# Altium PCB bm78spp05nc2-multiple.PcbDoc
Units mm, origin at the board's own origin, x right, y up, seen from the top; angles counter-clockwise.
Board outline 83.62 x 87.38 mm, 2 copper layers (Top Layer, Bottom Layer); 102 components, 12 nets, 410 pads, 156 vias.
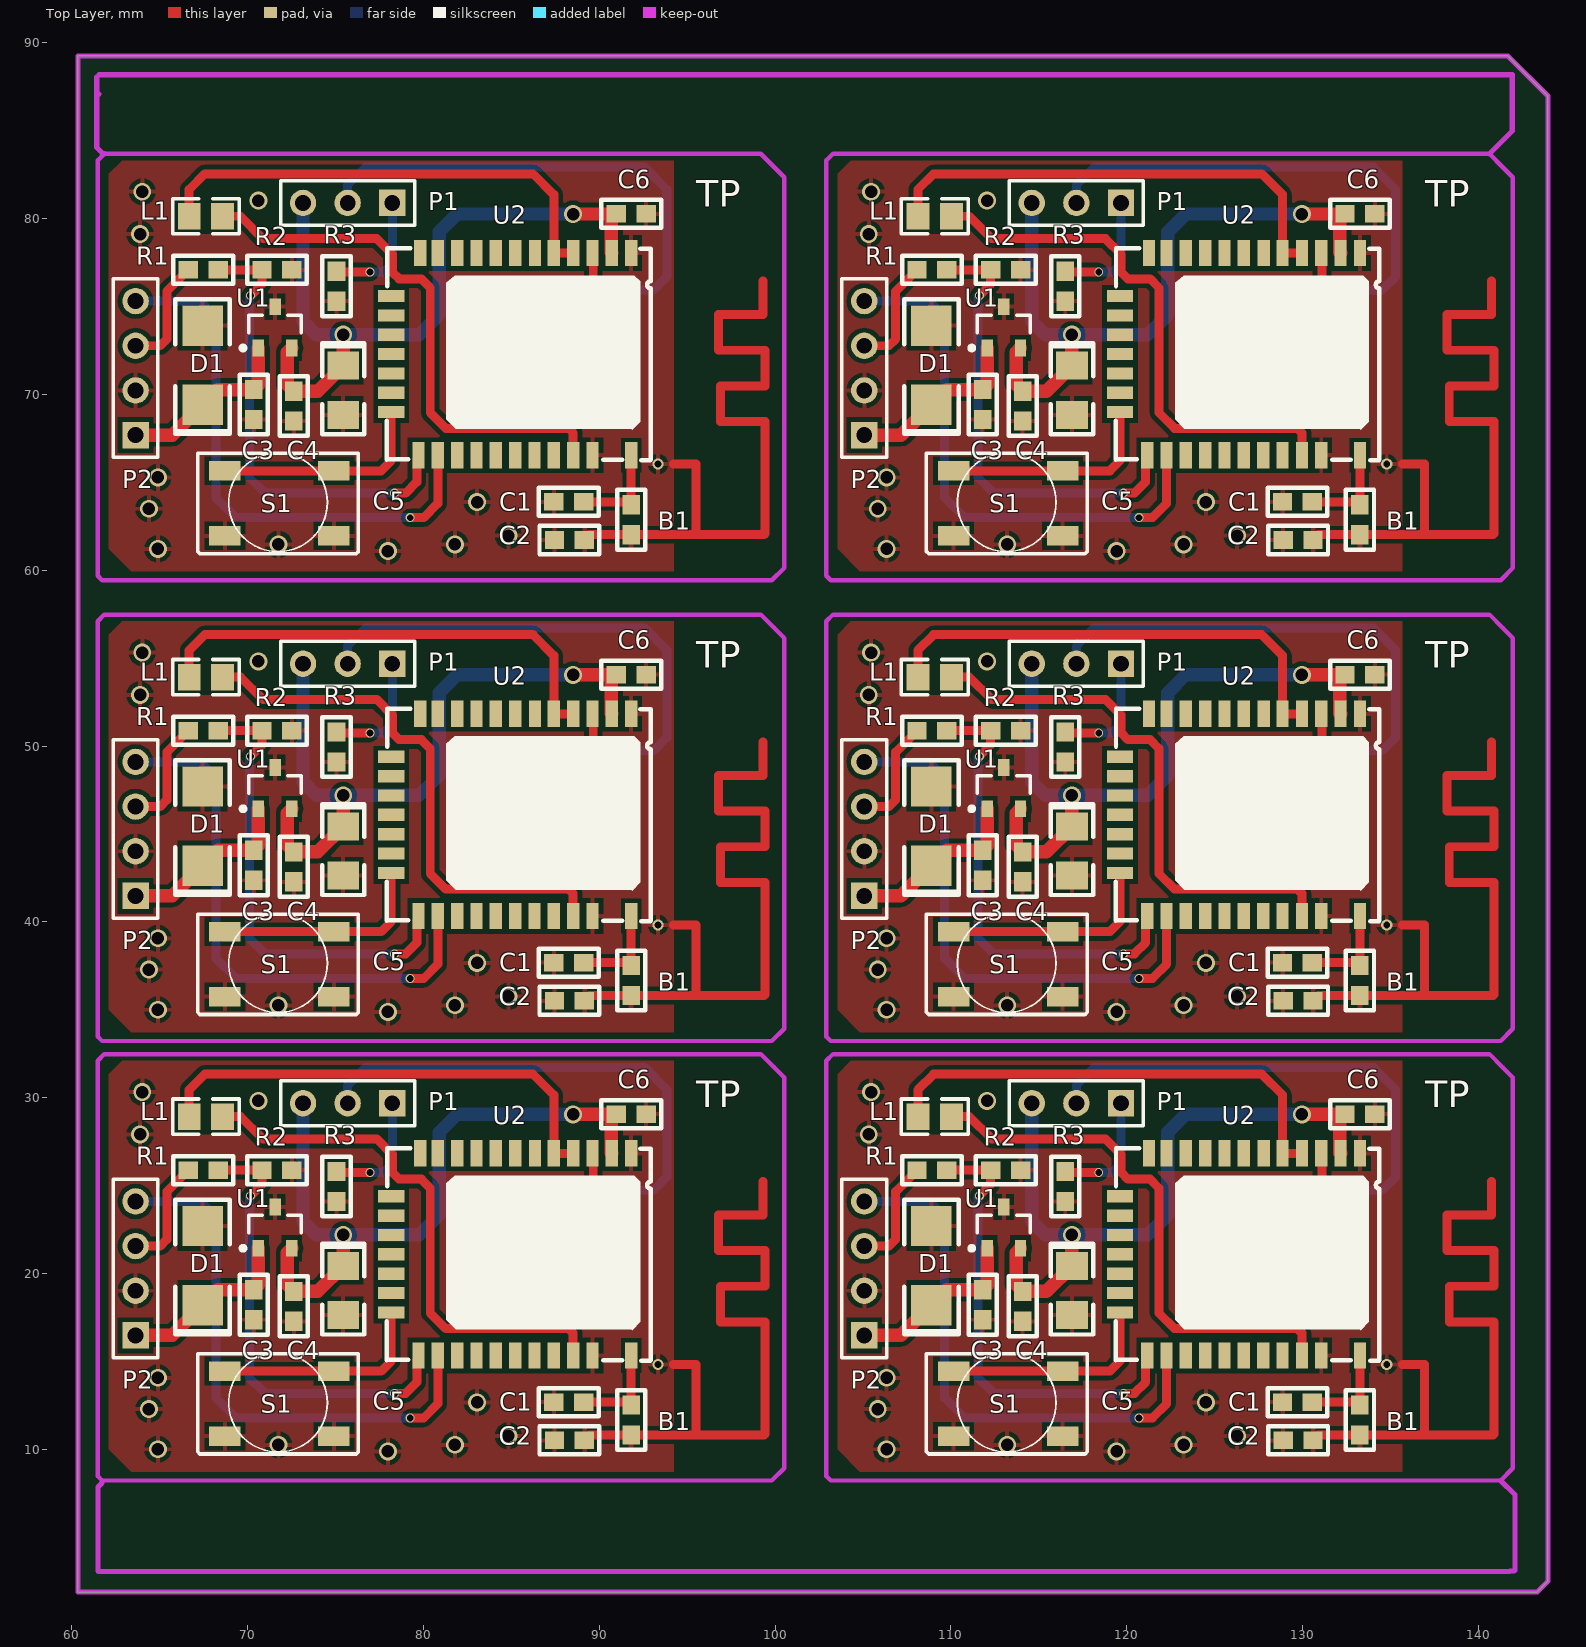
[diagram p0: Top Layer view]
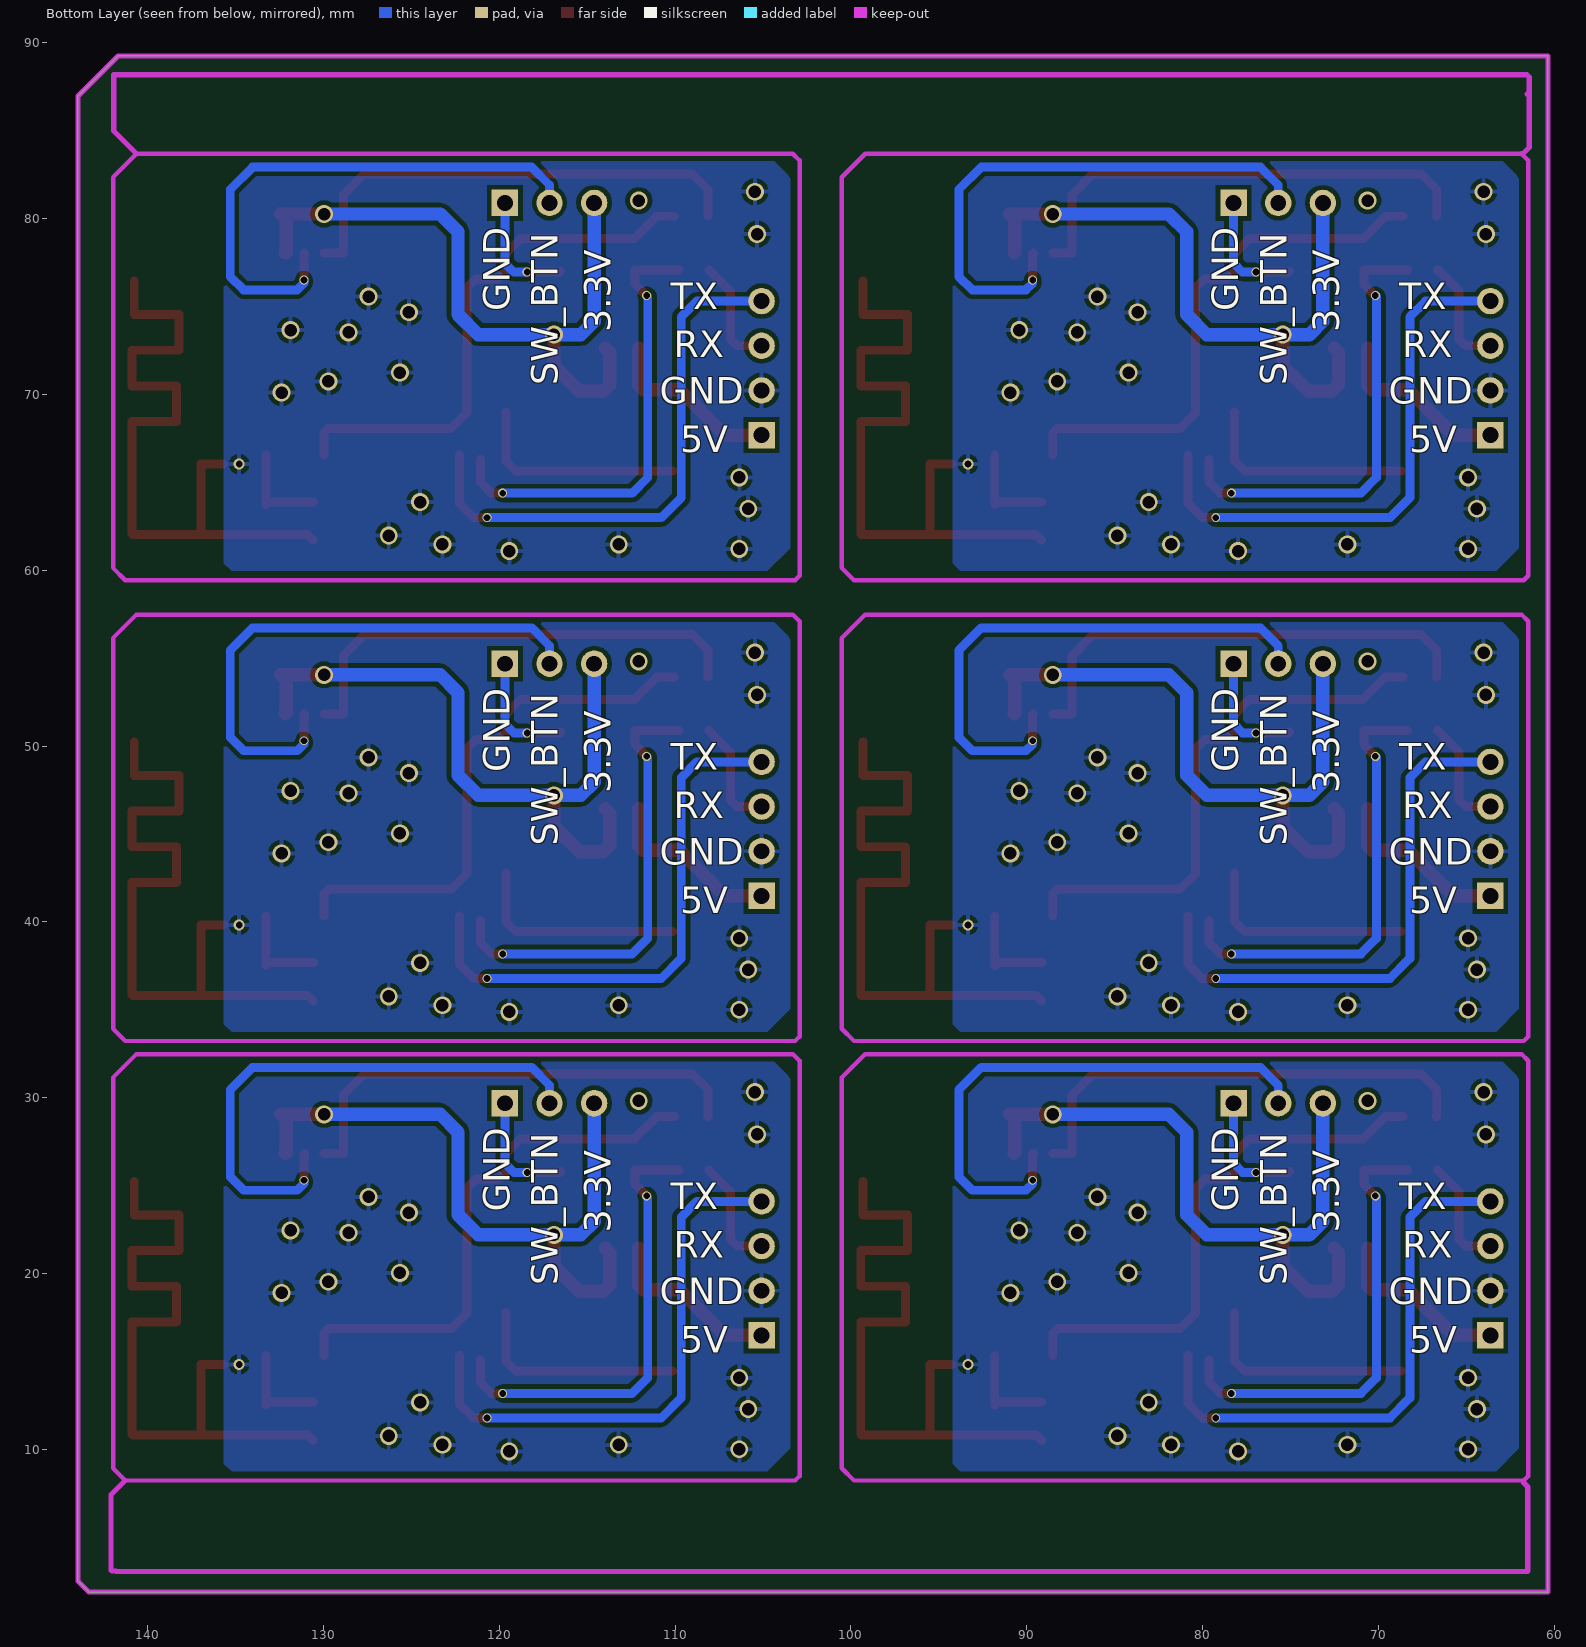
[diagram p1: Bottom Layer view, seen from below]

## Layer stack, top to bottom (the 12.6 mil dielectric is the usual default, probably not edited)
Top Solder: solder mask 0.0102, Solder Resist, Dk 3.5
Top Layer: signal copper 0.0356
Dielectric 1: dielectric 0.32, FR-4, Dk 4.8
Bottom Layer: signal copper 0.0356
Bottom Solder: solder mask 0.0102, Solder Resist, Dk 3.5

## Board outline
60.35,1.88 143.358,1.88 143.967,2.489 143.967,86.97 141.681,89.256 60.35,89.256

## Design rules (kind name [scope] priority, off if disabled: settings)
Clearance [All] p1: gap=0.254
PolygonConnect [All] p1: connectstyle=Relief reliefconductorwidth=0.254 reliefentries=4 polygonreliefangle="90 Angle" airgapwidth=0.254
RoutingVias [All] p1: holewidth=0.381 width=0.508 viastyle="Through Hole" minholewidth=0.381 minwidth=0.508 maxholewidth=0.711 maxwidth=1.016
SolderMaskExpansion [All] p1: expansion=0.102
Width [All] p1: maxlimit=1.016 minlimit=0.254 preferedwidth=0.508
30 further rules are at their usual default settings.

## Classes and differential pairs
component class BM78SPP05NC2: B1 C1 C2 C3 C4 C5 C6 D1 L1 P1 P2 R1 R2 R3 S1 U1 U2

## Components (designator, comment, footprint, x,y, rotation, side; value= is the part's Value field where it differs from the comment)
B1 "1nh" 0603 91.809,62.877 r270 top
B1 "1nh" 0603 133.262,62.877 r270 top
B1 "1nh" 0603 133.262,36.664 r270 top
B1 "1nh" 0603 91.809,36.664 r270 top
B1 "1nh" 0603 133.262,11.664 r270 top
B1 "1nh" 0603 91.809,11.664 r270 top
C1 "15pf" 0603 88.265,63.881 r0 top
C1 "15pf" 0603 129.718,63.881 r0 top
C1 "15pf" 0603 129.718,37.668 r0 top
C1 "15pf" 0603 88.265,37.668 r0 top
C1 "15pf" 0603 129.718,12.668 r0 top
C1 "15pf" 0603 88.265,12.668 r0 top
C2 "15pF" 0603 88.304,61.712 r0 top
C2 "15pF" 0603 129.757,61.712 r0 top
C2 "15pF" 0603 129.757,35.499 r0 top
C2 "15pF" 0603 88.304,35.499 r0 top
C2 "15pF" 0603 129.757,10.499 r0 top
C2 "15pF" 0603 88.304,10.499 r0 top
C3 "1uF" 0603 70.368,69.43 r90 top
C3 "1uF" 0603 111.821,69.43 r90 top
C3 "1uF" 0603 111.821,43.217 r90 top
C3 "1uF" 0603 70.368,43.217 r90 top
C3 "1uF" 0603 111.821,18.217 r90 top
C3 "1uF" 0603 70.368,18.217 r90 top
C4 "1uF" 0603 72.644,69.342 r90 top
C4 "1uF" 0603 114.097,69.342 r90 top
C4 "1uF" 0603 114.097,43.129 r90 top
C4 "1uF" 0603 72.644,43.129 r90 top
C4 "1uF" 0603 114.097,18.129 r90 top
C4 "1uF" 0603 72.644,18.129 r90 top
C5 "10uF/16V" 1206 75.438,70.231 r270 top
C5 "10uF/16V" 1206 116.891,70.231 r270 top
C5 "10uF/16V" 1206 116.891,44.018 r270 top
C5 "10uF/16V" 1206 75.438,44.018 r270 top
C5 "10uF/16V" 1206 116.891,19.018 r270 top
C5 "10uF/16V" 1206 75.438,19.018 r270 top
C6 "0.1uF" 0603 91.821,80.264 r0 top
C6 "0.1uF" 0603 133.274,80.264 r0 top
C6 "0.1uF" 0603 133.274,54.051 r0 top
C6 "0.1uF" 0603 91.821,54.051 r0 top
C6 "0.1uF" 0603 133.274,29.051 r0 top
C6 "0.1uF" 0603 91.821,29.051 r0 top
D1 "Schottky" DO214-AC 67.437,71.664 r270 top
D1 "Schottky" DO214-AC 108.89,71.664 r270 top
D1 "Schottky" DO214-AC 108.89,45.451 r270 top
D1 "Schottky" DO214-AC 67.437,45.451 r270 top
D1 "Schottky" DO214-AC 108.89,20.451 r270 top
D1 "Schottky" DO214-AC 67.437,20.451 r270 top
L1 "LED" 0805 67.63,80.137 r0 top
L1 "LED" 0805 109.083,80.137 r0 top
L1 "LED" 0805 109.083,53.924 r0 top
L1 "LED" 0805 67.63,53.924 r0 top
L1 "LED" 0805 109.083,28.924 r0 top
L1 "LED" 0805 67.63,28.924 r0 top
P1 "HC-SR501" Header3 75.692,78.629 r180 top
P1 "HC-SR501" Header3 117.145,78.629 r180 top
P1 "HC-SR501" Header3 117.145,52.416 r180 top
P1 "HC-SR501" Header3 75.692,52.416 r180 top
P1 "HC-SR501" Header3 117.145,27.416 r180 top
P1 "HC-SR501" Header3 75.692,27.416 r180 top
P2 "Header 4" HDR1X4 63.627,67.691 r90 top
P2 "Header 4" HDR1X4 105.08,67.691 r90 top
P2 "Header 4" HDR1X4 105.08,41.478 r90 top
P2 "Header 4" HDR1X4 63.627,41.478 r90 top
P2 "Header 4" HDR1X4 105.08,16.478 r90 top
P2 "Header 4" HDR1X4 63.627,16.478 r90 top
R1 "2.2K" 0603 67.476,77.079 r0 top
R1 "2.2K" 0603 108.929,77.079 r0 top
R1 "2.2K" 0603 108.929,50.866 r0 top
R1 "2.2K" 0603 67.476,50.866 r0 top
R1 "2.2K" 0603 108.929,25.866 r0 top
R1 "2.2K" 0603 67.476,25.866 r0 top
R2 "4.7K" 0603 71.667,77.099 r180 top
R2 "4.7K" 0603 113.12,77.099 r180 top
R2 "4.7K" 0603 113.12,50.886 r180 top
R2 "4.7K" 0603 71.667,50.886 r180 top
R2 "4.7K" 0603 113.12,25.886 r180 top
R2 "4.7K" 0603 71.667,25.886 r180 top
R3 "2.2K" 0603 75.067,76.161 r90 top
R3 "2.2K" 0603 116.52,76.161 r90 top
R3 "2.2K" 0603 116.52,49.948 r90 top
R3 "2.2K" 0603 75.067,49.948 r90 top
R3 "2.2K" 0603 116.52,24.948 r90 top
R3 "2.2K" 0603 75.067,24.948 r90 top
S1 "Button" BUtton-T4 74.907,61.959 r180 top
S1 "Button" BUtton-T4 116.36,61.959 r180 top
S1 "Button" BUtton-T4 116.36,35.746 r180 top
S1 "Button" BUtton-T4 74.907,35.746 r180 top
S1 "Button" BUtton-T4 116.36,10.746 r180 top
S1 "Button" BUtton-T4 74.907,10.746 r180 top
U1 "AP7313" AP7313-33SAG-7 71.562,73.819 r90 top
U1 "AP7313" AP7313-33SAG-7 113.015,73.819 r90 top
U1 "AP7313" AP7313-33SAG-7 113.015,47.606 r90 top
U1 "AP7313" AP7313-33SAG-7 71.562,47.606 r90 top
U1 "AP7313" AP7313-33SAG-7 113.015,22.606 r90 top
U1 "AP7313" AP7313-33SAG-7 71.562,22.606 r90 top
U2 "BM78SPP05NC2" BM78SPP05NC2 77.919,78.298 r270 top
U2 "BM78SPP05NC2" BM78SPP05NC2 119.372,78.298 r270 top
U2 "BM78SPP05NC2" BM78SPP05NC2 119.372,52.085 r270 top
U2 "BM78SPP05NC2" BM78SPP05NC2 77.919,52.085 r270 top
U2 "BM78SPP05NC2" BM78SPP05NC2 119.372,27.085 r270 top
U2 "BM78SPP05NC2" BM78SPP05NC2 77.919,27.085 r270 top

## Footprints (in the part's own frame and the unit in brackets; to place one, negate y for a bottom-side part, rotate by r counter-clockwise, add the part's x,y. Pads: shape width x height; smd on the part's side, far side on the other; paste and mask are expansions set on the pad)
0603 [mm]
  rect 1.1x1 smd: 1(-0.85,0.01) 2(0.85,0.01)
  silkscreen extent -1.7,-0.79 1.7,0.81
0805 [mm]
  rect 1.3x1.5 smd: 1(-0.95,0) 2(0.95,0)
  silkscreen extent -1.9,-1 1.9,1
1206 [mm]
  rect 1.6x1.8 smd: 1(-1.41,0) 2(1.39,0)
  silkscreen extent -2.68,-1.2 2.49,1.2
AP7313-33SAG-7 [mm] "SOT23, 3-Leads, Body 2.90x2.40mm, Pitch 0.95mm, IPC Medium Density"
  rect 0.95x0.65 smd: 1(-1.175,0.95) 2(-1.175,-0.95) 3(1.175,0)
  silkscreen extent -1.3,-1.5 0.7,1.95
BM78SPP05NC2 [mm]
  rect 1.5x0.7 smd: 1(0.25,13.9) 2(0.25,12.8) 3(0.25,11.7) 4(0.25,10.6) 5(0.25,9.5) 6(0.25,8.43) 7(0.25,7.3) 8(0.25,6.2) 9(0.25,5.1) 10(0.25,4) 11(0.25,2.9) 12(0.25,1.9) 20(11.75,1.8) 21(11.75,2.9) 22(11.75,4) 23(11.75,5.1) 24(11.75,6.2) 25(11.75,7.3) 26(11.75,8.4) 27(11.75,9.5) 28(11.75,10.6) 29(11.75,11.7) 30(11.75,13.9)
  rect 0.7x1.5 smd: 13(2.7,0.25) 14(3.8,0.25) 15(4.9,0.25) 16(6,0.25) 17(7.1,0.25) 18(8.2,0.25) 19(9.3,0.25)
  silkscreen extent -0.03,0 12.04,15.01
BUtton-T4 [mm] "4*4*1.5"
  rect 1.8x1.1 smd: 1(0,0) 1(6.2,0) 2(0,-3.7) 2(6.2,-3.7)
  silkscreen extent -1.4,-4.71 7.75,1.02
DO214-AC [mm]
  rect 2.3x2.3 smd: 1(-2.25,0) 2(2.25,0)
  silkscreen extent -3.75,-1.55 3.9,1.55
HDR1X4 [mm] "Connector; Header; 4 Position"
  rect 1.5x1.5 hole 0.9: 1(0,0)
  round 1.5 hole 0.9: 2(2.54,0) 3(5.08,0) 4(7.62,0)
  silkscreen extent -1.27,-1.27 8.89,1.27
Header3 [mm]
  rect 1.5x1.5 hole 0.9: 1(-2.54,-2.27)
  round 1.5 hole 0.9: 2(0,-2.27) 3(2.54,-2.27)
  silkscreen extent -3.81,-3.54 3.81,-1

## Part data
B1 B1 B1 B1 B1 B1: library part Bead
C1 C1 C1 C1 C1 C1 C2 C2 C2 C2 C2 C2 C3 C3 C3 C3 C3 C3 C4 C4 C4 C4 C4 C4 C6 C6 C6 C6 C6 C6: library part Cap1, "ceramic"
C5 C5 C5 C5 C5 C5: library part Cap3, "aluminum"
D1 D1 D1 D1 D1 D1: library part B340A-13-F
P1 P1 P1 P1 P1 P1: library part "Header 3", "Header, 3-Pin"
P2 P2 P2 P2 P2 P2: "Header, 4-Pin"
R1 R1 R1 R1 R1 R1 R2 R2 R2 R2 R2 R2 R3 R3 R3 R3 R3 R3: library part Res
U1 U1 U1 U1 U1 U1: library part AP7313-33SAG-7

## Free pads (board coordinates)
  round 1.524 on Keep-Out: 3(63.602,86.03) 4(138.278,5.817)

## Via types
v1: diameter 1.016, hole 0.711, Top Layer to Bottom Layer, 120 vias
v2: diameter 0.508, hole 0.381, Top Layer to Bottom Layer, 30 vias
v3: diameter 0.635, hole 0.381, Top Layer to Bottom Layer, 6 vias

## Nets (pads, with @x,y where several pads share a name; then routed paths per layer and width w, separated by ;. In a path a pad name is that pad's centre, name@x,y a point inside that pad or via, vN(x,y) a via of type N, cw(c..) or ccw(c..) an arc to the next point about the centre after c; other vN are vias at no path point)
3.3V: C4.2@72.634,70.192 C5.1@75.438,71.641 C6.1@90.971,80.274 P1.3@73.152,80.899 U1.2@72.512,72.644 U2.2@90.719,78.048 | length 40.7
  Top Layer w0.762: U1.2@72.512,72.644 72.263,72.395 72.263,70.563 72.634,70.192 73.989,70.192 75.438,71.641 v1(75.438,73.406) ; v1(88.519,80.264) C6.1@90.961,80.264 ; U2.2@90.719,78.048 90.678,78.089 90.678,79.981 C6.1@90.961,80.264 ; C6.1@90.971,80.274 C6.1@90.961,80.264
  Bottom Layer w0.762: P1.3@73.152,80.899 73.152,74.168 73.914,73.406 v1(75.438,73.406) 79.756,73.406 80.899,74.549 80.899,79.248 81.915,80.264 v1(88.519,80.264)
5V: C3.2@70.358,70.28 D1.2@67.437,69.414 P2.1@63.627,67.691 U1.1@70.612,72.644 | length 10.3
  Top Layer w0.762: P2.1@63.627,67.691 65.714,67.691 67.437,69.414 68.303,70.28 70.358,70.28 70.612,70.534 U1.1@70.612,72.644
ANT: B1.2@91.819,62.027 C1.1@87.415,63.891 C2.1@87.454,61.722 C2.2@89.154,61.722 C3.1@70.358,68.58 C4.1@72.634,68.492 C5.2@75.438,68.841 C6.2@92.671,80.274 D1.1@67.437,73.914 P2.2@63.627,70.231 R2.1@72.517,77.089 R3.1@75.057,75.311 S1.1@68.707,61.959 S1.1@74.907,61.959 U1.3@71.562,74.994 U2.1@91.819,78.048 U2.29@89.619,66.548 | length 40.4
  Top Layer w0.508: C2.2@89.154,61.722 89.459,62.027 91.819,62.027 95.504,62.027 ; 94.234,66.04 95.504,66.04 95.504,62.027 ; 99.314,76.454 99.314,74.549 96.774,74.549 96.774,72.517 99.441,72.517 99.441,70.485 96.901,70.485 96.901,68.453 99.441,68.453 99.441,62.078 99.39,62.027 95.504,62.027
  other v1: 77.978,61.087 64.897,61.214 71.755,61.468 81.788,61.468 84.836,61.976 64.389,63.5 83.058,63.881 64.897,65.278 90.932,70.104 88.265,70.739 84.201,71.247 87.122,73.533 90.424,73.66 83.693,74.676 85.979,75.565 63.881,79.121 64.008,81.534
  other v3: 93.345,66.04
LDO33_O: L1.1@66.68,80.137 U2.4@88.519,78.048 U2.5@87.419,78.048 | length 27.5
  Top Layer w0.508: L1.1@66.68,80.137 66.675,80.137 66.675,81.661 67.564,82.55 86.233,82.55 87.419,81.364 87.419,78.048 U2.4@88.519,78.048
LED1: L1.2@68.58,80.137 U2.28@88.519,66.548 | length 31.1
  Top Layer w0.508: L1.2@68.58,80.137 69.596,80.137 70.866,78.867 77.343,78.867 78.232,77.978 78.232,76.962 78.613,76.581 79.883,76.581 80.391,76.073 80.391,68.961 81.28,68.072 88.265,68.072 88.519,67.818 U2.28@88.519,66.548
NetB1_1: B1.1@91.819,63.727 C1.2@89.115,63.891 U2.30@91.819,66.548 | length 5.6
  Top Layer w0.508: C1.2@89.115,63.891 91.655,63.891 91.819,63.727 U2.30@91.819,66.548
NetP1_1: P1.1@78.232,80.899 R3.2@75.057,77.011 | length 6.8
  Top Layer w0.508: R3.2@75.057,77.011 75.106,76.962 v2(76.962,76.962)
  Bottom Layer w0.508: v2(76.962,76.962) 77.724,76.962 78.232,77.47 P1.1@78.232,80.899
NetR1_2: R1.2@68.326,77.089 R2.2@70.817,77.089 U2.20@79.719,66.548 | length 26
  Top Layer w0.508: R1.2@68.326,77.089 70.817,77.089 70.817,76.278 v2(70.168,75.629) ; v2(78.359,64.389) 78.994,64.389 79.629,65.024 U2.20@79.629,66.294
  Bottom Layer w0.508: v2(70.168,75.629) 70.104,75.565 70.104,65.278 70.993,64.389 v2(78.359,64.389)
NetS1_2: S1.2@68.707,65.659 S1.2@74.907,65.659 U2.19@78.169,68.998 | length 12.5
  Top Layer w0.508: S1.2@68.707,65.659 74.907,65.659 77.597,65.659 78.169,66.231 U2.19@78.169,68.998
RX: P2.3@63.627,72.771 R1.1@66.626,77.089 | length 6.4
  Top Layer w0.508: P2.3@63.627,72.771 65.024,72.771 65.405,73.152 65.405,75.868 R1.1@66.626,77.089
SW_BTN: P1.2@75.692,80.899 U2.3@89.619,78.048 | length 31.5
  Top Layer w0.508: U2.3@89.619,78.048 89.662,78.005 v2(89.662,76.517)
  Bottom Layer w0.508: P1.2@75.692,80.899 75.692,81.915 76.708,82.931 92.583,82.931 93.853,81.661 93.853,76.708 93.091,75.946 90.043,75.946 89.662,76.327 v2(89.662,76.517)
TX: P2.4@63.627,75.311 U2.21@80.819,66.548 | length 31.4
  Top Layer w0.508: v2(79.248,62.992) 80.01,62.992 80.819,63.801 U2.21@80.819,66.548
  Bottom Layer w0.508: P2.4@63.627,75.311 67.31,75.311 68.199,74.422 68.199,64.135 69.342,62.992 v2(79.248,62.992)
pads on no net: B1.1@91.819,12.514 B1.1@91.819,37.514 B1.1@133.272,12.514 B1.1@133.272,37.514 B1.1@133.272,63.727 B1.2@91.819,10.814 B1.2@91.819,35.814 B1.2@133.272,10.814 B1.2@133.272,35.814 B1.2@133.272,62.027 C1.1@87.415,12.678 C1.1@87.415,37.678 C1.1@128.868,12.678 C1.1@128.868,37.678 C1.1@128.868,63.891 C1.2@89.115,12.678 C1.2@89.115,37.678 C1.2@130.568,12.678 C1.2@130.568,37.678 C1.2@130.568,63.891 C2.1@87.454,10.509 C2.1@87.454,35.509 C2.1@128.907,10.509 C2.1@128.907,35.509 C2.1@128.907,61.722 C2.2@89.154,10.509 C2.2@89.154,35.509 C2.2@130.607,10.509 C2.2@130.607,35.509 C2.2@130.607,61.722 C3.1@70.358,17.367 C3.1@70.358,42.367 C3.1@111.811,17.367 C3.1@111.811,42.367 C3.1@111.811,68.58 C3.2@70.358,19.067 C3.2@70.358,44.067 C3.2@111.811,19.067 C3.2@111.811,44.067 C3.2@111.811,70.28 C4.1@72.634,17.279 C4.1@72.634,42.279 C4.1@114.087,17.279 C4.1@114.087,42.279 C4.1@114.087,68.492 C4.2@72.634,18.979 C4.2@72.634,43.979 C4.2@114.087,18.979 C4.2@114.087,43.979 C4.2@114.087,70.192 C5.1@75.438,20.428 C5.1@75.438,45.428 C5.1@116.891,20.428 C5.1@116.891,45.428 C5.1@116.891,71.641 C5.2@75.438,17.628 C5.2@75.438,42.628 C5.2@116.891,17.628 C5.2@116.891,42.628 C5.2@116.891,68.841 C6.1@90.971,29.061 C6.1@90.971,54.061 C6.1@132.424,29.061 C6.1@132.424,54.061 C6.1@132.424,80.274 C6.2@92.671,29.061 C6.2@92.671,54.061 C6.2@134.124,29.061 C6.2@134.124,54.061 C6.2@134.124,80.274 D1.1@67.437,22.701 D1.1@67.437,47.701 D1.1@108.89,22.701 D1.1@108.89,47.701 D1.1@108.89,73.914 D1.2@67.437,18.201 D1.2@67.437,43.201 D1.2@108.89,18.201 D1.2@108.89,43.201 D1.2@108.89,69.414 L1.1@66.68,28.924 L1.1@66.68,53.924 L1.1@108.133,28.924 L1.1@108.133,53.924 L1.1@108.133,80.137 L1.2@68.58,28.924 L1.2@68.58,53.924 L1.2@110.033,28.924 L1.2@110.033,53.924 L1.2@110.033,80.137 P1.1@78.232,29.686 P1.1@78.232,54.686 P1.1@119.685,29.686 P1.1@119.685,54.686 P1.1@119.685,80.899 P1.2@75.692,29.686 P1.2@75.692,54.686 P1.2@117.145,29.686 P1.2@117.145,54.686 P1.2@117.145,80.899 P1.3@73.152,29.686 P1.3@73.152,54.686 P1.3@114.605,29.686 P1.3@114.605,54.686 P1.3@114.605,80.899 P2.1@63.627,16.478 P2.1@63.627,41.478 P2.1@105.08,16.478 P2.1@105.08,41.478 P2.1@105.08,67.691 P2.2@63.627,19.018 P2.2@63.627,44.018 P2.2@105.08,19.018 P2.2@105.08,44.018 P2.2@105.08,70.231 P2.3@63.627,21.558 P2.3@63.627,46.558 P2.3@105.08,21.558 P2.3@105.08,46.558 P2.3@105.08,72.771 P2.4@63.627,24.098 P2.4@63.627,49.098 P2.4@105.08,24.098 P2.4@105.08,49.098 P2.4@105.08,75.311 R1.1@66.626,25.876 R1.1@66.626,50.876 R1.1@108.079,25.876 R1.1@108.079,50.876 R1.1@108.079,77.089 R1.2@68.326,25.876 R1.2@68.326,50.876 R1.2@109.779,25.876 R1.2@109.779,50.876 R1.2@109.779,77.089 R2.1@72.517,25.876 R2.1@72.517,50.876 R2.1@113.97,25.876 R2.1@113.97,50.876 R2.1@113.97,77.089 R2.2@70.817,25.876 R2.2@70.817,50.876 R2.2@112.27,25.876 R2.2@112.27,50.876 R2.2@112.27,77.089 R3.1@75.057,24.098 R3.1@75.057,49.098 R3.1@116.51,24.098 R3.1@116.51,49.098 R3.1@116.51,75.311 R3.2@75.057,25.798 R3.2@75.057,50.798 R3.2@116.51,25.798 R3.2@116.51,50.798 R3.2@116.51,77.011 S1.1@68.707,10.746 S1.1@68.707,35.746 S1.1@74.907,10.746 S1.1@74.907,35.746 S1.1@110.16,10.746 S1.1@110.16,35.746 S1.1@110.16,61.959 S1.1@116.36,10.746 S1.1@116.36,35.746 S1.1@116.36,61.959 S1.2@68.707,14.446 S1.2@68.707,39.446 S1.2@74.907,14.446 S1.2@74.907,39.446 S1.2@110.16,14.446 S1.2@110.16,39.446 S1.2@110.16,65.659 S1.2@116.36,14.446 S1.2@116.36,39.446 S1.2@116.36,65.659 U1.1@70.612,21.431 U1.1@70.612,46.431 U1.1@112.065,21.431 U1.1@112.065,46.431 U1.1@112.065,72.644 U1.2@72.512,21.431 U1.2@72.512,46.431 U1.2@113.965,21.431 U1.2@113.965,46.431 U1.2@113.965,72.644 U1.3@71.562,23.781 U1.3@71.562,48.781 U1.3@113.015,23.781 U1.3@113.015,48.781 U1.3@113.015,74.994 U2.1@91.819,26.835 U2.1@91.819,51.835 U2.1@133.272,26.835 U2.1@133.272,51.835 U2.1@133.272,78.048 U2.2@90.719,26.835 U2.2@90.719,51.835 U2.2@132.172,26.835 U2.2@132.172,51.835 U2.2@132.172,78.048 U2.3@89.619,26.835 U2.3@89.619,51.835 U2.3@131.072,26.835 U2.3@131.072,51.835 U2.3@131.072,78.048 U2.4@88.519,26.835 U2.4@88.519,51.835 U2.4@129.972,26.835 U2.4@129.972,51.835 U2.4@129.972,78.048 U2.5@87.419,26.835 U2.5@87.419,51.835 U2.5@128.872,26.835 U2.5@128.872,51.835 U2.5@128.872,78.048 U2.6 U2.7 U2.8 U2.9 U2.10 U2.11 U2.12 U2.13 U2.14 U2.15 U2.16 U2.17 U2.18 U2.19@78.169,17.785 U2.19@78.169,42.785 U2.19@119.622,17.785 U2.19@119.622,42.785 U2.19@119.622,68.998 U2.20@79.719,15.335 U2.20@79.719,40.335 U2.20@121.172,15.335 U2.20@121.172,40.335 U2.20@121.172,66.548 U2.21@80.819,15.335 U2.21@80.819,40.335 U2.21@122.272,15.335 U2.21@122.272,40.335 U2.21@122.272,66.548 U2.22 U2.23 U2.24 U2.25 U2.26 U2.27 U2.28@88.519,15.335 U2.28@88.519,40.335 U2.28@129.972,15.335 U2.28@129.972,40.335 U2.28@129.972,66.548 U2.29@89.619,15.335 U2.29@89.619,40.335 U2.29@131.072,15.335 U2.29@131.072,40.335 U2.29@131.072,66.548 U2.30@91.819,15.335 U2.30@91.819,40.335 U2.30@133.272,15.335 U2.30@133.272,40.335 U2.30@133.272,66.548
copper on no net: | length 1350.7
  Top Layer w0.508: 63.627,21.558 65.024,21.558 65.405,21.939 65.405,24.655 66.626,25.876 ; 63.627,46.558 65.024,46.558 65.405,46.939 65.405,49.655 66.626,50.876 ; 66.68,28.924 66.675,28.924 66.675,30.448 67.564,31.337 86.233,31.337 87.419,30.151 87.419,26.835 88.519,26.835 ; 66.68,53.924 66.675,53.924 66.675,55.448 67.564,56.337 86.233,56.337 87.419,55.151 87.419,51.835 88.519,51.835 ; 68.326,25.876 70.817,25.876 70.817,25.065 v2(70.168,24.416) ; 68.326,50.876 70.817,50.876 70.817,50.065 v2(70.168,49.416) ; 68.58,28.924 69.596,28.924 70.866,27.654 77.343,27.654 78.232,26.765 78.232,25.749 78.613,25.368 79.883,25.368 80.391,24.86 80.391,17.748 81.28,16.859 88.265,16.859 88.519,16.605 88.519,15.335 ; 68.58,53.924 69.596,53.924 70.866,52.654 77.343,52.654 78.232,51.765 78.232,50.749 78.613,50.368 79.883,50.368 80.391,49.86 80.391,42.748 81.28,41.859 88.265,41.859 88.519,41.605 88.519,40.335 ; 68.707,14.446 74.907,14.446 77.597,14.446 78.169,15.018 78.169,17.785 ; 68.707,39.446 74.907,39.446 77.597,39.446 78.169,40.018 78.169,42.785 ; 75.057,25.798 75.106,25.749 v2(76.962,25.749) ; 75.057,50.798 75.106,50.749 v2(76.962,50.749) ; v2(78.359,13.176) 78.994,13.176 79.629,13.811 79.629,15.081 ; v2(78.359,38.176) 78.994,38.176 79.629,38.811 79.629,40.081 ; v2(79.248,11.779) 80.01,11.779 80.819,12.588 80.819,15.335 ; v2(79.248,36.779) 80.01,36.779 80.819,37.588 80.819,40.335 ; 89.115,12.678 91.655,12.678 91.819,12.514 91.819,15.335 ; 89.115,37.678 91.655,37.678 91.819,37.514 91.819,40.335 ; 89.154,10.509 89.459,10.814 91.819,10.814 95.504,10.814 ; 89.154,35.509 89.459,35.814 91.819,35.814 95.504,35.814 ; 89.619,26.835 89.662,26.792 v2(89.662,25.305) ; 89.619,51.835 89.662,51.792 v2(89.662,50.305) ; 94.234,14.827 95.504,14.827 95.504,10.814 ; 94.234,39.827 95.504,39.827 95.504,35.814 ; 99.314,25.241 99.314,23.336 96.774,23.336 96.774,21.304 99.441,21.304 99.441,19.272 96.901,19.272 96.901,17.24 99.441,17.24 99.441,10.865 99.39,10.814 95.504,10.814 ; 99.314,50.241 99.314,48.336 96.774,48.336 96.774,46.304 99.441,46.304 99.441,44.272 96.901,44.272 96.901,42.24 99.441,42.24 99.441,35.865 99.39,35.814 95.504,35.814 ; 105.08,21.558 106.477,21.558 106.858,21.939 106.858,24.655 108.079,25.876 ; 105.08,46.558 106.477,46.558 106.858,46.939 106.858,49.655 108.079,50.876 ; 105.08,72.771 106.477,72.771 106.858,73.152 106.858,75.868 108.079,77.089 ; 108.133,28.924 108.128,28.924 108.128,30.448 109.017,31.337 127.686,31.337 128.872,30.151 128.872,26.835 129.972,26.835 ; 108.133,53.924 108.128,53.924 108.128,55.448 109.017,56.337 127.686,56.337 128.872,55.151 128.872,51.835 129.972,51.835 ; 108.133,80.137 108.128,80.137 108.128,81.661 109.017,82.55 127.686,82.55 128.872,81.364 128.872,78.048 129.972,78.048 ; 109.779,25.876 112.27,25.876 112.27,25.065 v2(111.62,24.416) ; 109.779,50.876 112.27,50.876 112.27,50.065 v2(111.62,49.416) ; 109.779,77.089 112.27,77.089 112.27,76.278 v2(111.62,75.629) ; 110.033,28.924 111.049,28.924 112.319,27.654 118.796,27.654 119.685,26.765 119.685,25.749 120.066,25.368 121.336,25.368 121.844,24.86 121.844,17.748 122.733,16.859 129.718,16.859 129.972,16.605 129.972,15.335 ; 110.033,53.924 111.049,53.924 112.319,52.654 118.796,52.654 119.685,51.765 119.685,50.749 120.066,50.368 121.336,50.368 121.844,49.86 121.844,42.748 122.733,41.859 129.718,41.859 129.972,41.605 129.972,40.335 ; 110.033,80.137 111.049,80.137 112.319,78.867 118.796,78.867 119.685,77.978 119.685,76.962 120.066,76.581 121.336,76.581 121.844,76.073 121.844,68.961 122.733,68.072 129.718,68.072 129.972,67.818 129.972,66.548 ; 110.16,14.446 116.36,14.446 119.05,14.446 119.622,15.018 119.622,17.785 ; 110.16,39.446 116.36,39.446 119.05,39.446 119.622,40.018 119.622,42.785 ; 110.16,65.659 116.36,65.659 119.05,65.659 119.622,66.231 119.622,68.998 ; 116.51,25.798 116.559,25.749 v2(118.415,25.749) ; 116.51,50.798 116.559,50.749 v2(118.415,50.749) ; 116.51,77.011 116.559,76.962 v2(118.415,76.962) ; v2(119.812,13.176) 120.447,13.176 121.082,13.811 121.082,15.081 ; v2(119.812,38.176) 120.447,38.176 121.082,38.811 121.082,40.081 ; v2(119.812,64.389) 120.447,64.389 121.082,65.024 121.082,66.294 ; v2(120.701,11.779) 121.463,11.779 122.272,12.588 122.272,15.335 ; v2(120.701,36.779) 121.463,36.779 122.272,37.588 122.272,40.335 ; v2(120.701,62.992) 121.463,62.992 122.272,63.801 122.272,66.548 ; 130.568,12.678 133.108,12.678 133.272,12.514 133.272,15.335 ; 130.568,37.678 133.108,37.678 133.272,37.514 133.272,40.335 ; 130.568,63.891 133.108,63.891 133.272,63.727 133.272,66.548 ; 130.607,10.509 130.912,10.814 133.272,10.814 136.957,10.814 ; 130.607,35.509 130.912,35.814 133.272,35.814 136.957,35.814 ; 130.607,61.722 130.912,62.027 133.272,62.027 136.957,62.027 ; 131.072,26.835 131.115,26.792 v2(131.115,25.305) ; 131.072,51.835 131.115,51.792 v2(131.115,50.305) ; 131.072,78.048 131.115,78.005 v2(131.115,76.517) ; 135.687,14.827 136.957,14.827 136.957,10.814 ; 135.687,39.827 136.957,39.827 136.957,35.814 ; 135.687,66.04 136.957,66.04 136.957,62.027 ; 140.767,25.241 140.767,23.336 138.227,23.336 138.227,21.304 140.894,21.304 140.894,19.272 138.354,19.272 138.354,17.24 140.894,17.24 140.894,10.865 140.843,10.814 136.957,10.814 ; 140.767,50.241 140.767,48.336 138.227,48.336 138.227,46.304 140.894,46.304 140.894,44.272 138.354,44.272 138.354,42.24 140.894,42.24 140.894,35.865 140.843,35.814 136.957,35.814 ; 140.767,76.454 140.767,74.549 138.227,74.549 138.227,72.517 140.894,72.517 140.894,70.485 138.354,70.485 138.354,68.453 140.894,68.453 140.894,62.078 140.843,62.027 136.957,62.027
  Top Layer w0.762: 63.627,16.478 65.714,16.478 67.437,18.201 68.303,19.067 70.358,19.067 70.612,19.321 70.612,21.431 ; 63.627,41.478 65.714,41.478 67.437,43.201 68.303,44.067 70.358,44.067 70.612,44.321 70.612,46.431 ; 72.512,21.431 72.263,21.182 72.263,19.35 72.634,18.979 73.989,18.979 75.438,20.428 v1(75.438,22.193) ; 72.512,46.431 72.263,46.182 72.263,44.35 72.634,43.979 73.989,43.979 75.438,45.428 v1(75.438,47.193) ; v1(88.519,29.051) 90.961,29.051 ; v1(88.519,54.051) 90.961,54.051 ; 90.719,26.835 90.678,26.876 90.678,28.768 90.961,29.051 ; 90.719,51.835 90.678,51.876 90.678,53.768 90.961,54.051 ; 90.971,29.061 90.961,29.051 ; 90.971,54.061 90.961,54.051 ; 105.08,16.478 107.167,16.478 108.89,18.201 109.756,19.067 111.811,19.067 112.065,19.321 112.065,21.431 ; 105.08,41.478 107.167,41.478 108.89,43.201 109.756,44.067 111.811,44.067 112.065,44.321 112.065,46.431 ; 105.08,67.691 107.167,67.691 108.89,69.414 109.756,70.28 111.811,70.28 112.065,70.534 112.065,72.644 ; 113.965,21.431 113.716,21.182 113.716,19.35 114.087,18.979 115.442,18.979 116.891,20.428 v1(116.891,22.193) ; 113.965,46.431 113.716,46.182 113.716,44.35 114.087,43.979 115.442,43.979 116.891,45.428 v1(116.891,47.193) ; 113.965,72.644 113.716,72.395 113.716,70.563 114.087,70.192 115.442,70.192 116.891,71.641 v1(116.891,73.406) ; v1(129.972,29.051) 132.414,29.051 ; v1(129.972,54.051) 132.414,54.051 ; v1(129.972,80.264) 132.414,80.264 ; 132.172,26.835 132.131,26.876 132.131,28.768 132.414,29.051 ; 132.172,51.835 132.131,51.876 132.131,53.768 132.414,54.051 ; 132.172,78.048 132.131,78.089 132.131,79.981 132.414,80.264 ; 132.424,29.061 132.414,29.051 ; 132.424,54.061 132.414,54.051 ; 132.424,80.274 132.414,80.264
  Bottom Layer w0.508: 63.627,24.098 67.31,24.098 68.199,23.209 68.199,12.922 69.342,11.779 v2(79.248,11.779) ; 63.627,49.098 67.31,49.098 68.199,48.209 68.199,37.922 69.342,36.779 v2(79.248,36.779) ; v2(70.168,24.416) 70.104,24.352 70.104,14.065 70.993,13.176 v2(78.359,13.176) ; v2(70.168,49.416) 70.104,49.352 70.104,39.065 70.993,38.176 v2(78.359,38.176) ; 75.692,29.686 75.692,30.702 76.708,31.718 92.583,31.718 93.853,30.448 93.853,25.495 93.091,24.733 90.043,24.733 89.662,25.114 v2(89.662,25.305) ; 75.692,54.686 75.692,55.702 76.708,56.718 92.583,56.718 93.853,55.448 93.853,50.495 93.091,49.733 90.043,49.733 89.662,50.114 v2(89.662,50.305) ; v2(76.962,25.749) 77.724,25.749 78.232,26.257 78.232,29.686 ; v2(76.962,50.749) 77.724,50.749 78.232,51.257 78.232,54.686 ; 105.08,24.098 108.763,24.098 109.652,23.209 109.652,12.922 110.795,11.779 v2(120.701,11.779) ; 105.08,49.098 108.763,49.098 109.652,48.209 109.652,37.922 110.795,36.779 v2(120.701,36.779) ; 105.08,75.311 108.763,75.311 109.652,74.422 109.652,64.135 110.795,62.992 v2(120.701,62.992) ; v2(111.62,24.416) 111.557,24.352 111.557,14.065 112.446,13.176 v2(119.812,13.176) ; v2(111.62,49.416) 111.557,49.352 111.557,39.065 112.446,38.176 v2(119.812,38.176) ; v2(111.62,75.629) 111.557,75.565 111.557,65.278 112.446,64.389 v2(119.812,64.389) ; 117.145,29.686 117.145,30.702 118.161,31.718 134.036,31.718 135.306,30.448 135.306,25.495 134.544,24.733 131.496,24.733 131.115,25.114 v2(131.115,25.305) ; 117.145,54.686 117.145,55.702 118.161,56.718 134.036,56.718 135.306,55.448 135.306,50.495 134.544,49.733 131.496,49.733 131.115,50.114 v2(131.115,50.305) ; 117.145,80.899 117.145,81.915 118.161,82.931 134.036,82.931 135.306,81.661 135.306,76.708 134.544,75.946 131.496,75.946 131.115,76.327 v2(131.115,76.517) ; v2(118.415,25.749) 119.177,25.749 119.685,26.257 119.685,29.686 ; v2(118.415,50.749) 119.177,50.749 119.685,51.257 119.685,54.686 ; v2(118.415,76.962) 119.177,76.962 119.685,77.47 119.685,80.899
  Bottom Layer w0.762: 73.152,29.686 73.152,22.955 73.914,22.193 v1(75.438,22.193) 79.756,22.193 80.899,23.336 80.899,28.035 81.915,29.051 v1(88.519,29.051) ; 73.152,54.686 73.152,47.955 73.914,47.193 v1(75.438,47.193) 79.756,47.193 80.899,48.336 80.899,53.035 81.915,54.051 v1(88.519,54.051) ; 114.605,29.686 114.605,22.955 115.367,22.193 v1(116.891,22.193) 121.209,22.193 122.352,23.336 122.352,28.035 123.368,29.051 v1(129.972,29.051) ; 114.605,54.686 114.605,47.955 115.367,47.193 v1(116.891,47.193) 121.209,47.193 122.352,48.336 122.352,53.035 123.368,54.051 v1(129.972,54.051) ; 114.605,80.899 114.605,74.168 115.367,73.406 v1(116.891,73.406) 121.209,73.406 122.352,74.549 122.352,79.248 123.368,80.264 v1(129.972,80.264)
  other v1: 77.978,9.874 119.431,9.874 64.897,10.001 106.35,10.001 71.755,10.255 81.788,10.255 113.208,10.255 123.241,10.255 84.836,10.763 126.289,10.763 64.389,12.287 105.842,12.287 83.058,12.668 124.511,12.668 64.897,14.065 106.35,14.065 90.932,18.891 132.385,18.891 88.265,19.526 129.718,19.526 84.201,20.034 125.654,20.034 87.122,22.32 128.575,22.32 90.424,22.447 131.877,22.447 83.693,23.463 125.146,23.463 85.979,24.352 127.432,24.352 63.881,27.908 105.334,27.908 70.612,29.813 112.065,29.813 64.008,30.321 105.461,30.321 77.978,34.874 119.431,34.874 64.897,35.001 106.35,35.001 71.755,35.255 81.788,35.255 113.208,35.255 123.241,35.255 84.836,35.763 126.289,35.763 64.389,37.287 105.842,37.287 83.058,37.668 124.511,37.668 64.897,39.065 106.35,39.065 90.932,43.891 132.385,43.891 88.265,44.526 129.718,44.526 84.201,45.034 125.654,45.034 87.122,47.32 128.575,47.32 90.424,47.447 131.877,47.447 83.693,48.463 125.146,48.463 85.979,49.352 127.432,49.352 63.881,52.908 105.334,52.908 70.612,54.813 112.065,54.813 64.008,55.321 105.461,55.321 119.431,61.087 106.35,61.214 113.208,61.468 123.241,61.468 126.289,61.976 105.842,63.5 124.511,63.881 106.35,65.278 132.385,70.104 129.718,70.739 125.654,71.247 128.575,73.533 131.877,73.66 125.146,74.676 127.432,75.565 105.334,79.121 70.612,81.026 112.065,81.026 105.461,81.534
  other v3: 93.345,14.827 134.798,14.827 93.345,39.827 134.798,39.827 134.798,66.04

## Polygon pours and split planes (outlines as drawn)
ANT on Top Layer "GND" (solid, remove dead copper, pour order 0): 62.103,82.55 62.865,83.312 94.234,83.312 94.234,80.645 94.234,78.359 94.234,60.96 94.234,60.452 94.234,59.944 63.627,59.944 63.373,59.944 62.103,61.214 62.103,69.85
no net on Top Layer "GND" (solid, remove dead copper, pour order 4): 103.556,82.55 104.318,83.312 135.687,83.312 135.687,80.645 135.687,78.359 135.687,60.96 135.687,60.452 135.687,59.944 105.08,59.944 104.826,59.944 103.556,61.214 103.556,69.85
no net on Top Layer "GND" (solid, remove dead copper, pour order 8): 103.556,56.337 104.318,57.099 135.687,57.099 135.687,54.432 135.687,52.146 135.687,34.747 135.687,34.239 135.687,33.731 105.08,33.731 104.826,33.731 103.556,35.001 103.556,43.637
no net on Top Layer "GND" (solid, remove dead copper, pour order 10): 62.103,56.337 62.865,57.099 94.234,57.099 94.234,54.432 94.234,52.146 94.234,34.747 94.234,34.239 94.234,33.731 63.627,33.731 63.373,33.731 62.103,35.001 62.103,43.637
no net on Top Layer "GND" (solid, remove dead copper, pour order 16): 103.556,31.337 104.318,32.099 135.687,32.099 135.687,29.432 135.687,27.146 135.687,9.747 135.687,9.239 135.687,8.731 105.08,8.731 104.826,8.731 103.556,10.001 103.556,18.637
no net on Top Layer "GND" (solid, remove dead copper, pour order 18): 62.103,31.337 62.865,32.099 94.234,32.099 94.234,29.432 94.234,27.146 94.234,9.747 94.234,9.239 94.234,8.731 63.627,8.731 63.373,8.731 62.103,10.001 62.103,18.637
ANT on Bottom Layer "GND" (solid, remove dead copper, pour order 2): 62.154,82.499 62.916,83.261 94.005,83.261 94.209,83.058 94.209,60.477 94.209,60.401 93.777,59.969 63.297,59.969 62.052,61.214 62.001,61.265 62.001,81.94 62.001,82.271
no net on Bottom Layer "GND" (solid, remove dead copper, pour order 6): 103.607,82.499 104.369,83.261 135.458,83.261 135.661,83.058 135.661,60.477 135.661,60.401 135.23,59.969 104.75,59.969 103.505,61.214 103.454,61.265 103.454,81.94 103.454,82.271
no net on Bottom Layer "GND" (solid, remove dead copper, pour order 12): 103.607,56.286 104.369,57.048 135.458,57.048 135.661,56.845 135.661,34.265 135.661,34.188 135.23,33.757 104.75,33.757 103.505,35.001 103.454,35.052 103.454,55.728 103.454,56.058
no net on Bottom Layer "GND" (solid, remove dead copper, pour order 14): 62.154,56.286 62.916,57.048 94.005,57.048 94.209,56.845 94.209,34.265 94.209,34.188 93.777,33.757 63.297,33.757 62.052,35.001 62.001,35.052 62.001,55.728 62.001,56.058
no net on Bottom Layer "GND" (solid, remove dead copper, pour order 20): 103.607,31.286 104.369,32.048 135.458,32.048 135.661,31.845 135.661,9.265 135.661,9.188 135.23,8.757 104.75,8.757 103.505,10.001 103.454,10.052 103.454,30.728 103.454,31.058
no net on Bottom Layer "GND" (solid, remove dead copper, pour order 22): 62.154,31.286 62.916,32.048 94.005,32.048 94.209,31.845 94.209,9.265 94.209,9.188 93.777,8.757 63.297,8.757 62.052,10.001 62.001,10.052 62.001,30.728 62.001,31.058

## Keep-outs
Keep-Out Layer:
  lines w0.254: 61.468,8.477 61.722,8.223 99.822,8.223 100.52,8.922 100.52,23.4 100.52,31.147 99.949,31.718 99.187,32.48 61.849,32.48 61.468,32.099 61.468,26.352 61.468,14.351 61.468,8.477 ; 61.468,33.477 61.722,33.223 99.822,33.223 100.52,33.922 100.52,48.4 100.52,56.147 99.949,56.718 99.187,57.48 61.849,57.48 61.468,57.099 61.468,51.352 61.468,39.351 61.468,33.477 ; 61.468,59.69 61.468,65.564 61.468,77.565 61.468,83.312 61.849,83.693 99.187,83.693 99.949,82.931 100.52,82.359 100.52,74.612 100.52,60.134 99.822,59.436 61.722,59.436 61.468,59.69 ; 102.921,8.477 102.921,14.351 102.921,26.352 102.921,32.099 103.302,32.48 140.64,32.48 141.402,31.718 141.973,31.147 141.973,23.4 141.973,8.922 141.275,8.223 103.175,8.223 102.921,8.477 ; 102.921,33.477 102.921,39.351 102.921,51.352 102.921,57.099 103.302,57.48 140.64,57.48 141.402,56.718 141.973,56.147 141.973,48.4 141.973,33.922 141.275,33.223 103.175,33.223 102.921,33.477 ; 102.921,59.69 103.175,59.436 141.275,59.436 141.973,60.134 141.973,74.612 141.973,82.359 141.402,82.931 140.64,83.693 103.302,83.693 102.921,83.312 102.921,77.565 102.921,65.564 102.921,59.69
  lines w0.3: 61.417,88.062 61.417,86.97 ; 61.544,87.097 61.417,86.97 ; 61.544,88.189 81.642,88.189 121.837,88.189 141.935,88.189 141.935,87.097 141.935,84.988 140.64,83.693 ; 61.722,8.223 61.722,8.077 61.493,7.849 61.493,3.073 61.519,3.048 141.783,3.048 141.808,3.073 142.037,3.073 142.088,3.124 142.088,7.41 141.275,8.223 ; 61.849,83.693 61.773,83.693 61.417,84.049 61.417,86.462 61.417,86.97 ; 60.35,1.88 60.35,89.256 141.681,89.256 143.967,86.97 143.967,6.045 143.967,2.489 143.358,1.88 60.35,1.88

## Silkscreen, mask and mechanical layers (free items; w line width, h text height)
Top Overlay:
  region: 81.305,76.352 81.788,76.759 81.864,76.759 91.999,76.759 92.329,76.429 92.329,68.453 91.872,67.996 91.821,68.047 81.839,68.047 81.305,68.58
  region: 122.758,76.352 123.241,76.759 123.317,76.759 133.452,76.759 133.782,76.429 133.782,68.453 133.325,67.996 133.274,68.047 123.292,68.047 122.758,68.58
  region: 122.758,50.14 123.241,50.546 123.317,50.546 133.452,50.546 133.782,50.216 133.782,42.24 133.325,41.783 133.274,41.834 123.292,41.834 122.758,42.367
  region: 81.305,50.14 81.788,50.546 81.864,50.546 91.999,50.546 92.329,50.216 92.329,42.24 91.872,41.783 91.821,41.834 81.839,41.834 81.305,42.367
  region: 122.758,25.14 123.241,25.546 123.317,25.546 133.452,25.546 133.782,25.216 133.782,17.24 133.325,16.783 133.274,16.834 123.292,16.834 122.758,17.367
  region: 81.305,25.14 81.788,25.546 81.864,25.546 91.999,25.546 92.329,25.216 92.329,17.24 91.872,16.783 91.821,16.834 81.839,16.834 81.305,17.367
  text "TP" at 95.529,80.67 h1.52
  text "TP" at 136.982,80.67 h1.52
  text "TP" at 95.529,54.458 h1.52
  text "TP" at 136.982,54.458 h1.52
  text "TP" at 95.529,29.458 h1.52
  text "TP" at 136.982,29.458 h1.52
Bottom Overlay:
  text "TX" at 68.809,74.854 h1.52
  text "TX" at 110.261,74.854 h1.52
  text "GND" at 77.953,74.727 h1.52 r270
  text "GND" at 119.405,74.727 h1.52 r270
  text "3.3V" at 72.212,73.533 h1.52 r270
  text "3.3V" at 113.665,73.533 h1.52 r270
  text "RX" at 68.631,72.111 h1.52
  text "RX" at 110.084,72.111 h1.52
  text "SW_BTN" at 75.209,70.536 h1.52 r270
  text "SW_BTN" at 116.662,70.536 h1.52 r270
  text "GND" at 69.418,69.469 h1.52
  text "GND" at 110.871,69.469 h1.52
  text "5V" at 68.25,66.7 h1.52
  text "5V" at 109.703,66.7 h1.52
  text "TX" at 68.809,48.641 h1.52
  text "TX" at 110.261,48.641 h1.52
  text "GND" at 77.953,48.514 h1.52 r270
  text "GND" at 119.405,48.514 h1.52 r270
  text "3.3V" at 72.212,47.32 h1.52 r270
  text "3.3V" at 113.665,47.32 h1.52 r270
  text "RX" at 68.631,45.898 h1.52
  text "RX" at 110.084,45.898 h1.52
  text "SW_BTN" at 75.209,44.323 h1.52 r270
  text "SW_BTN" at 116.662,44.323 h1.52 r270
  text "GND" at 69.418,43.256 h1.52
  text "GND" at 110.871,43.256 h1.52
  text "5V" at 68.25,40.488 h1.52
  text "5V" at 109.703,40.488 h1.52
  text "TX" at 68.809,23.641 h1.52
  text "TX" at 110.261,23.641 h1.52
  text "GND" at 77.953,23.514 h1.52 r270
  text "GND" at 119.405,23.514 h1.52 r270
  text "3.3V" at 72.212,22.32 h1.52 r270
  text "3.3V" at 113.665,22.32 h1.52 r270
  text "RX" at 68.631,20.898 h1.52
  text "RX" at 110.084,20.898 h1.52
  text "SW_BTN" at 75.209,19.323 h1.52 r270
  text "SW_BTN" at 116.662,19.323 h1.52 r270
  text "GND" at 69.418,18.256 h1.52
  text "GND" at 110.871,18.256 h1.52
  text "5V" at 68.25,15.488 h1.52
  text "5V" at 109.703,15.488 h1.52
Top Paste:
  lines w0.5: 91.923,10.814 95.91,10.814 99.339,10.814 99.441,10.916 99.441,17.266 99.416,17.24 96.901,17.24 96.901,19.272 99.441,19.272 99.441,21.304 96.799,21.304 96.774,21.33 96.774,23.336 99.314,23.336 99.314,25.241 ; 91.923,35.814 95.91,35.814 99.339,35.814 99.441,35.916 99.441,42.266 99.416,42.24 96.901,42.24 96.901,44.272 99.441,44.272 99.441,46.304 96.799,46.304 96.774,46.33 96.774,48.336 99.314,48.336 99.314,50.241 ; 91.923,62.027 95.91,62.027 99.339,62.027 99.441,62.128 99.441,68.478 99.416,68.453 96.901,68.453 96.901,70.485 99.441,70.485 99.441,72.517 96.799,72.517 96.774,72.542 96.774,74.549 99.314,74.549 99.314,76.454 ; 133.375,10.814 137.363,10.814 140.792,10.814 140.894,10.916 140.894,17.266 140.868,17.24 138.354,17.24 138.354,19.272 140.894,19.272 140.894,21.304 138.252,21.304 138.227,21.33 138.227,23.336 140.767,23.336 140.767,25.241 ; 133.375,35.814 137.363,35.814 140.792,35.814 140.894,35.916 140.894,42.266 140.868,42.24 138.354,42.24 138.354,44.272 140.894,44.272 140.894,46.304 138.252,46.304 138.227,46.33 138.227,48.336 140.767,48.336 140.767,50.241 ; 133.375,62.027 137.363,62.027 140.792,62.027 140.894,62.128 140.894,68.478 140.868,68.453 138.354,68.453 138.354,70.485 140.894,70.485 140.894,72.517 138.252,72.517 138.227,72.542 138.227,74.549 140.767,74.549 140.767,76.454
  lines w0.6: 94.513,14.853 95.479,14.853 95.504,14.827 95.504,10.814 ; 94.513,39.853 95.479,39.853 95.504,39.827 95.504,35.814 ; 94.513,66.065 95.479,66.065 95.504,66.04 95.504,62.027 ; 135.966,14.853 136.931,14.853 136.957,14.827 136.957,10.814 ; 135.966,39.853 136.931,39.853 136.957,39.827 136.957,35.814 ; 135.966,66.065 136.931,66.065 136.957,66.04 136.957,62.027
Top Solder:
  lines w0.6: 91.821,10.839 99.416,10.839 99.441,10.865 99.441,17.266 99.416,17.24 96.926,17.24 96.901,17.266 96.901,19.298 99.466,19.298 99.441,19.323 99.441,21.304 99.39,21.355 96.749,21.355 96.774,21.38 96.774,23.336 99.365,23.336 99.314,23.387 99.314,25.216 ; 91.821,35.839 99.416,35.839 99.441,35.865 99.441,42.266 99.416,42.24 96.926,42.24 96.901,42.266 96.901,44.298 99.466,44.298 99.441,44.323 99.441,46.304 99.39,46.355 96.749,46.355 96.774,46.38 96.774,48.336 99.365,48.336 99.314,48.387 99.314,50.216 ; 91.821,62.052 99.416,62.052 99.441,62.078 99.441,68.478 99.416,68.453 96.926,68.453 96.901,68.478 96.901,70.51 99.466,70.51 99.441,70.536 99.441,72.517 99.39,72.568 96.749,72.568 96.774,72.593 96.774,74.549 99.365,74.549 99.314,74.6 99.314,76.429 ; 94.488,14.853 95.479,14.853 95.504,14.827 95.504,11.068 ; 94.488,39.853 95.479,39.853 95.504,39.827 95.504,36.068 ; 94.488,66.065 95.479,66.065 95.504,66.04 95.504,62.281 ; 133.274,10.839 140.868,10.839 140.894,10.865 140.894,17.266 140.868,17.24 138.379,17.24 138.354,17.266 138.354,19.298 140.919,19.298 140.894,19.323 140.894,21.304 140.843,21.355 138.201,21.355 138.227,21.38 138.227,23.336 140.818,23.336 140.767,23.387 140.767,25.216 ; 133.274,35.839 140.868,35.839 140.894,35.865 140.894,42.266 140.868,42.24 138.379,42.24 138.354,42.266 138.354,44.298 140.919,44.298 140.894,44.323 140.894,46.304 140.843,46.355 138.201,46.355 138.227,46.38 138.227,48.336 140.818,48.336 140.767,48.387 140.767,50.216 ; 133.274,62.052 140.868,62.052 140.894,62.078 140.894,68.478 140.868,68.453 138.379,68.453 138.354,68.478 138.354,70.51 140.919,70.51 140.894,70.536 140.894,72.517 140.843,72.568 138.201,72.568 138.227,72.593 138.227,74.549 140.818,74.549 140.767,74.6 140.767,76.429 ; 135.941,14.853 136.931,14.853 136.957,14.827 136.957,11.068 ; 135.941,39.853 136.931,39.853 136.957,39.827 136.957,36.068 ; 135.941,66.065 136.931,66.065 136.957,66.04 136.957,62.281

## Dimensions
60.35,89.256 to 143.967,86.97 on Top Overlay
141.681,89.256 to 143.358,1.88 on Top Overlay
